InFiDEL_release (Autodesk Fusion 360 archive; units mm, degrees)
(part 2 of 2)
sketch "Sketch42" plane through (0, 0, -12.5) normal (0, 0, -1) x axis (1, 0, 0)
  line L1 (43.0529, -11.2074) -> (41.7955, -15.3363)
  curve K1 (43.2824, -10.9315) -> (43.0529, -11.2074)
  curve K2 (43.6391, -10.8945) -> (43.2824, -10.9315)
  line L2 (44.3673, -11.1162) -> (43.6391, -10.8945)
  curve K3 (44.6383, -11.3454) -> (44.3673, -11.1162)
  curve K4 (44.6643, -11.6992) -> (44.6383, -11.3454)
  line L3 (42.3458, -19.3124) -> (44.6643, -11.6992)
  curve K5 (42.1325, -19.5782) -> (42.3458, -19.3124)
  curve K6 (41.7789, -19.6156) -> (42.1325, -19.5782)
  line L4 (41.0358, -19.3893) -> (41.7789, -19.6156)
  curve K7 (40.7665, -19.156) -> (41.0358, -19.3893)
  curve K8 (40.7367, -18.813) -> (40.7665, -19.156)
  line L5 (40.7788, -18.6732) -> (40.7367, -18.813)
  curve K9 (39.6654, -18.874) -> (40.7788, -18.6732)
  curve K10 (38.3581, -18.6736) -> (39.6654, -18.874)
  curve K11 (36.5327, -17.1841) -> (38.3581, -18.6736)
  curve K12 (36.6028, -14.6019) -> (36.5327, -17.1841)
  line L6 (38.0961, -9.6984) -> (36.6028, -14.6019)
  curve K13 (38.3257, -9.4223) -> (38.0961, -9.6984)
  curve K14 (38.6824, -9.385) -> (38.3257, -9.4223)
  line L7 (39.3956, -9.6022) -> (38.6824, -9.385)
  curve K15 (39.6726, -9.8309) -> (39.3956, -9.6022)
  curve K16 (39.7079, -10.1887) -> (39.6726, -9.8309)
  line L8 (38.4271, -14.3945) -> (39.7079, -10.1887)
  line L9 (0, 0.8665) -> (2.0813, 0.2327)
  line L10 (0, -22) -> (0, 0.8665)
  line L11 (43.8534, -22) -> (0, -22)
  line L12 (46.793, -12.3472) -> (43.8534, -22)
  curve K17 (47.0029, -12.0701) -> (46.793, -12.3472)
  curve K18 (47.35, -12.0246) -> (47.0029, -12.0701)
  line L13 (48.1677, -12.2736) -> (47.35, -12.0246)
  curve K19 (48.4321, -12.5038) -> (48.1677, -12.2736)
  curve K20 (48.4503, -12.8519) -> (48.4321, -12.5038)
  line L14 (45.6644, -22) -> (48.4503, -12.8519)
  line L15 (50, -22) -> (45.6644, -22)
  line L16 (50, 2) -> (50, -22)
  line L17 (1.6466, 2) -> (50, 2)
  curve K21 (2.5546, 1.7334) -> (1.6466, 2)
  curve K22 (3.7364, 1.273) -> (2.5546, 1.7334)
  curve K23 (4.6822, 0.5429) -> (3.7364, 1.273)
  curve K24 (5.1744, -0.5786) -> (4.6822, 0.5429)
  curve K25 (4.9882, -2.2066) -> (5.1744, -0.5786)
  line L18 (2.5164, -10.3235) -> (4.9882, -2.2066)
  curve K26 (2.293, -10.5875) -> (2.5164, -10.3235)
  curve K27 (1.9343, -10.6218) -> (2.293, -10.5875)
  line L19 (1.176, -10.3909) -> (1.9343, -10.6218)
  curve K28 (0.8989, -10.1616) -> (1.176, -10.3909)
  curve K29 (0.8591, -9.8185) -> (0.8989, -10.1616)
  line L20 (3.3328, -1.6957) -> (0.8591, -9.8185)
  curve K30 (3.4789, -0.9974) -> (3.3328, -1.6957)
  curve K31 (3.3842, -0.5) -> (3.4789, -0.9974)
  curve K32 (2.9657, -0.1182) -> (3.3842, -0.5)
  curve K33 (2.0813, 0.2327) -> (2.9657, -0.1182)
  curve K34 (22.7149, -16.723) -> (22.7545, -17.0665)
  line L21 (23.0791, -15.5271) -> (22.7149, -16.723)
  curve K35 (23.3088, -15.2502) -> (23.0791, -15.5271)
  curve K36 (23.666, -15.2128) -> (23.3088, -15.2502)
  line L22 (24.4243, -15.4438) -> (23.666, -15.2128)
  curve K37 (24.7016, -15.6729) -> (24.4243, -15.4438)
  curve K38 (24.7364, -16.0318) -> (24.7016, -15.6729)
  line L23 (24.3722, -17.2277) -> (24.7364, -16.0318)
  curve K39 (24.1487, -17.4924) -> (24.3722, -17.2277)
  curve K40 (23.79, -17.5268) -> (24.1487, -17.4924)
  line L24 (23.0316, -17.2959) -> (23.79, -17.5268)
  curve K41 (22.7545, -17.0665) -> (23.0316, -17.2959)
  curve K42 (23.6897, -13.631) -> (23.7295, -13.9741)
  line L25 (26.0082, -6.0178) -> (23.6897, -13.631)
  curve K43 (26.2378, -5.7412) -> (26.0082, -6.0178)
  curve K44 (26.5947, -5.7039) -> (26.2378, -5.7412)
  line L26 (27.3079, -5.9211) -> (26.5947, -5.7039)
  curve K45 (27.585, -6.1502) -> (27.3079, -5.9211)
  curve K46 (27.6199, -6.5086) -> (27.585, -6.1502)
  line L27 (25.3014, -14.1218) -> (27.6199, -6.5086)
  curve K47 (25.078, -14.3861) -> (25.3014, -14.1218)
  curve K48 (24.7196, -14.4205) -> (25.078, -14.3861)
  line L28 (24.0064, -14.2033) -> (24.7196, -14.4205)
  curve K49 (23.7295, -13.9741) -> (24.0064, -14.2033)
  curve K50 (7.3751, -1.0358) -> (7.5956, -1.4466)
  line L29 (7.6051, -0.2805) -> (7.3751, -1.0358)
  curve K51 (7.7394, -0.0762) -> (7.6051, -0.2805)
  curve K52 (8.0125, -0.0118) -> (7.7394, -0.0762)
  curve K53 (8.5792, -0.1431) -> (8.0125, -0.0118)
  curve K54 (9.3638, -0.3569) -> (8.5792, -0.1431)
  curve K55 (10.1986, -0.5945) -> (9.3638, -0.3569)
  line L30 (10.9476, -0.8226) -> (10.1986, -0.5945)
  curve K56 (13.2215, -2.2584) -> (10.9476, -0.8226)
  curve K57 (13.381, -4.763) -> (13.2215, -2.2584)
  line L31 (11.6314, -10.5084) -> (13.381, -4.763)
  curve K58 (10.1082, -12.4846) -> (11.6314, -10.5084)
  curve K59 (7.4193, -12.4085) -> (10.1082, -12.4846)
  curve K60 (6.7389, -12.1918) -> (7.4193, -12.4085)
  curve K61 (5.872, -11.91) -> (6.7389, -12.1918)
  curve K62 (5.1061, -11.6512) -> (5.872, -11.91)
  curve K63 (4.5236, -11.4251) -> (5.1061, -11.6512)
  curve K64 (4.3429, -11.223) -> (4.5236, -11.4251)
  curve K65 (4.3429, -10.9929) -> (4.3429, -11.223)
  line L32 (4.5714, -10.2426) -> (4.3429, -10.9929)
  curve K66 (4.9887, -10.0068) -> (4.5714, -10.2426)
  line L33 (7.8674, -10.8835) -> (4.9887, -10.0068)
  curve K67 (8.7961, -11.0832) -> (7.8674, -10.8835)
  curve K68 (9.3618, -11.0016) -> (8.7961, -11.0832)
  curve K69 (9.7105, -10.6553) -> (9.3618, -11.0016)
  curve K70 (9.9754, -9.9992) -> (9.7105, -10.6553)
  line L34 (10.5641, -8.0661) -> (9.9754, -9.9992)
  line L35 (6.137, -6.7179) -> (10.5641, -8.0661)
  curve K71 (5.8591, -6.4896) -> (6.137, -6.7179)
  curve K72 (5.8184, -6.1476) -> (5.8591, -6.4896)
  line L36 (5.9899, -5.5846) -> (5.8184, -6.1476)
  curve K73 (6.2198, -5.3096) -> (5.9899, -5.5846)
  curve K74 (6.5768, -5.2734) -> (6.2198, -5.3096)
  line L37 (11.004, -6.6217) -> (6.5768, -5.2734)
  line L38 (11.7242, -4.2569) -> (11.004, -6.6217)
  curve K75 (11.871, -3.5559) -> (11.7242, -4.2569)
  curve K76 (11.7769, -3.0569) -> (11.871, -3.5559)
  curve K77 (11.3586, -2.6744) -> (11.7769, -3.0569)
  curve K78 (10.4742, -2.3233) -> (11.3586, -2.6744)
  line L39 (7.5956, -1.4466) -> (10.4742, -2.3233)
  curve K79 (14.1152, -9.2264) -> (13.7966, -11.452)
  line L40 (14.7287, -7.2118) -> (14.1152, -9.2264)
  curve K80 (15.7052, -5.1903) -> (14.7287, -7.2118)
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extrude "Extrude7" cut sketch "Sketch42" against normal blind 1
position "Position6"
sketch "Sketch43" plane through (0, 0, -12.5) normal (0, 0, -1) x axis (1, 0, 0)
  line L1 (43.0529, -11.2074) -> (41.7955, -15.3363)
  curve K1 (43.2824, -10.9315) -> (43.0529, -11.2074)
  curve K2 (43.6391, -10.8945) -> (43.2824, -10.9315)
  line L2 (44.3673, -11.1162) -> (43.6391, -10.8945)
  curve K3 (44.6383, -11.3454) -> (44.3673, -11.1162)
  curve K4 (44.6643, -11.6992) -> (44.6383, -11.3454)
  line L3 (42.3458, -19.3124) -> (44.6643, -11.6992)
  curve K5 (42.1325, -19.5782) -> (42.3458, -19.3124)
  curve K6 (41.7789, -19.6156) -> (42.1325, -19.5782)
  line L4 (41.0358, -19.3893) -> (41.7789, -19.6156)
  curve K7 (40.7665, -19.156) -> (41.0358, -19.3893)
  curve K8 (40.7367, -18.813) -> (40.7665, -19.156)
  line L5 (40.7788, -18.6732) -> (40.7367, -18.813)
  curve K9 (39.6654, -18.874) -> (40.7788, -18.6732)
  curve K10 (38.3581, -18.6736) -> (39.6654, -18.874)
  curve K11 (36.5327, -17.1841) -> (38.3581, -18.6736)
  curve K12 (36.6028, -14.6019) -> (36.5327, -17.1841)
  line L6 (38.0961, -9.6984) -> (36.6028, -14.6019)
  curve K13 (38.3257, -9.4223) -> (38.0961, -9.6984)
  curve K14 (38.6824, -9.385) -> (38.3257, -9.4223)
  line L7 (39.3956, -9.6022) -> (38.6824, -9.385)
  curve K15 (39.6726, -9.8309) -> (39.3956, -9.6022)
  curve K16 (39.7079, -10.1887) -> (39.6726, -9.8309)
  line L8 (38.4271, -14.3945) -> (39.7079, -10.1887)
  line L9 (0, 0.8665) -> (2.0813, 0.2327)
  line L10 (0, -22) -> (0, 0.8665)
  line L11 (43.8534, -22) -> (0, -22)
  line L12 (46.793, -12.3472) -> (43.8534, -22)
  curve K17 (47.0029, -12.0701) -> (46.793, -12.3472)
  curve K18 (47.35, -12.0246) -> (47.0029, -12.0701)
  line L13 (48.1677, -12.2736) -> (47.35, -12.0246)
  curve K19 (48.4321, -12.5038) -> (48.1677, -12.2736)
  curve K20 (48.4503, -12.8519) -> (48.4321, -12.5038)
  line L14 (45.6644, -22) -> (48.4503, -12.8519)
  line L15 (50, -22) -> (45.6644, -22)
  line L16 (50, 2) -> (50, -22)
  line L17 (1.6466, 2) -> (50, 2)
  curve K21 (2.5546, 1.7334) -> (1.6466, 2)
  curve K22 (3.7364, 1.273) -> (2.5546, 1.7334)
  curve K23 (4.6822, 0.5429) -> (3.7364, 1.273)
  curve K24 (5.1744, -0.5786) -> (4.6822, 0.5429)
  curve K25 (4.9882, -2.2066) -> (5.1744, -0.5786)
  line L18 (2.5164, -10.3235) -> (4.9882, -2.2066)
  curve K26 (2.293, -10.5875) -> (2.5164, -10.3235)
  curve K27 (1.9343, -10.6218) -> (2.293, -10.5875)
  line L19 (1.176, -10.3909) -> (1.9343, -10.6218)
  curve K28 (0.8989, -10.1616) -> (1.176, -10.3909)
  curve K29 (0.8591, -9.8185) -> (0.8989, -10.1616)
  line L20 (3.3328, -1.6957) -> (0.8591, -9.8185)
  curve K30 (3.4789, -0.9974) -> (3.3328, -1.6957)
  curve K31 (3.3842, -0.5) -> (3.4789, -0.9974)
  curve K32 (2.9657, -0.1182) -> (3.3842, -0.5)
  curve K33 (2.0813, 0.2327) -> (2.9657, -0.1182)
  curve K34 (22.7149, -16.723) -> (22.7545, -17.0665)
  line L21 (23.0791, -15.5271) -> (22.7149, -16.723)
  curve K35 (23.3088, -15.2502) -> (23.0791, -15.5271)
  curve K36 (23.666, -15.2128) -> (23.3088, -15.2502)
  line L22 (24.4243, -15.4438) -> (23.666, -15.2128)
  curve K37 (24.7016, -15.6729) -> (24.4243, -15.4438)
  curve K38 (24.7364, -16.0318) -> (24.7016, -15.6729)
  line L23 (24.3722, -17.2277) -> (24.7364, -16.0318)
  curve K39 (24.1487, -17.4924) -> (24.3722, -17.2277)
  curve K40 (23.79, -17.5268) -> (24.1487, -17.4924)
  line L24 (23.0316, -17.2959) -> (23.79, -17.5268)
  curve K41 (22.7545, -17.0665) -> (23.0316, -17.2959)
  curve K42 (23.6897, -13.631) -> (23.7295, -13.9741)
  line L25 (26.0082, -6.0178) -> (23.6897, -13.631)
  curve K43 (26.2378, -5.7412) -> (26.0082, -6.0178)
  curve K44 (26.5947, -5.7039) -> (26.2378, -5.7412)
  line L26 (27.3079, -5.9211) -> (26.5947, -5.7039)
  curve K45 (27.585, -6.1502) -> (27.3079, -5.9211)
  curve K46 (27.6199, -6.5086) -> (27.585, -6.1502)
  line L27 (25.3014, -14.1218) -> (27.6199, -6.5086)
  curve K47 (25.078, -14.3861) -> (25.3014, -14.1218)
  curve K48 (24.7196, -14.4205) -> (25.078, -14.3861)
  line L28 (24.0064, -14.2033) -> (24.7196, -14.4205)
  curve K49 (23.7295, -13.9741) -> (24.0064, -14.2033)
  curve K50 (7.3751, -1.0358) -> (7.5956, -1.4466)
  line L29 (7.6051, -0.2805) -> (7.3751, -1.0358)
  curve K51 (7.7394, -0.0762) -> (7.6051, -0.2805)
  curve K52 (8.0125, -0.0118) -> (7.7394, -0.0762)
  curve K53 (8.5792, -0.1431) -> (8.0125, -0.0118)
  curve K54 (9.3638, -0.3569) -> (8.5792, -0.1431)
  curve K55 (10.1986, -0.5945) -> (9.3638, -0.3569)
  line L30 (10.9476, -0.8226) -> (10.1986, -0.5945)
  curve K56 (13.2215, -2.2584) -> (10.9476, -0.8226)
  curve K57 (13.381, -4.763) -> (13.2215, -2.2584)
  line L31 (11.6314, -10.5084) -> (13.381, -4.763)
  curve K58 (10.1082, -12.4846) -> (11.6314, -10.5084)
  curve K59 (7.4193, -12.4085) -> (10.1082, -12.4846)
  curve K60 (6.7389, -12.1918) -> (7.4193, -12.4085)
  curve K61 (5.872, -11.91) -> (6.7389, -12.1918)
  curve K62 (5.1061, -11.6512) -> (5.872, -11.91)
  curve K63 (4.5236, -11.4251) -> (5.1061, -11.6512)
  curve K64 (4.3429, -11.223) -> (4.5236, -11.4251)
  curve K65 (4.3429, -10.9929) -> (4.3429, -11.223)
  line L32 (4.5714, -10.2426) -> (4.3429, -10.9929)
  curve K66 (4.9887, -10.0068) -> (4.5714, -10.2426)
  line L33 (7.8674, -10.8835) -> (4.9887, -10.0068)
  curve K67 (8.7961, -11.0832) -> (7.8674, -10.8835)
  curve K68 (9.3618, -11.0016) -> (8.7961, -11.0832)
  curve K69 (9.7105, -10.6553) -> (9.3618, -11.0016)
  curve K70 (9.9754, -9.9992) -> (9.7105, -10.6553)
  line L34 (10.5641, -8.0661) -> (9.9754, -9.9992)
  line L35 (6.137, -6.7179) -> (10.5641, -8.0661)
  curve K71 (5.8591, -6.4896) -> (6.137, -6.7179)
  curve K72 (5.8184, -6.1476) -> (5.8591, -6.4896)
  line L36 (5.9899, -5.5846) -> (5.8184, -6.1476)
  curve K73 (6.2198, -5.3096) -> (5.9899, -5.5846)
  curve K74 (6.5768, -5.2734) -> (6.2198, -5.3096)
  line L37 (11.004, -6.6217) -> (6.5768, -5.2734)
  line L38 (11.7242, -4.2569) -> (11.004, -6.6217)
  curve K75 (11.871, -3.5559) -> (11.7242, -4.2569)
  curve K76 (11.7769, -3.0569) -> (11.871, -3.5559)
  curve K77 (11.3586, -2.6744) -> (11.7769, -3.0569)
  curve K78 (10.4742, -2.3233) -> (11.3586, -2.6744)
  line L39 (7.5956, -1.4466) -> (10.4742, -2.3233)
  curve K79 (14.1152, -9.2264) -> (13.7966, -11.452)
  line L40 (14.7287, -7.2118) -> (14.1152, -9.2264)
  curve K80 (15.7052, -5.1903) -> (14.7287, -7.2118)
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  point P172 (0.5507, 0.6988)
  point P41 (1.6466, 2)
  point P176 (1.6466, 2)
  coincident L9 P172
  coincident P41 P176
extrude "Extrude8" cut sketch "Sketch43" to an object
sketch "Sketch44" plane through (0, -2, 0) normal (0, -1, 0) x axis (1, 0, 0)
  curve K1 (39.523, -8.8538) -> (26.677, -8.8538)
  line L1 (21.1, 2) -> (21.1, -2)
  curve K2 (26.677, 8.8538) -> (39.523, 8.8538)
  line L2 (45.1, -2) -> (45.1, 2)
  line L3 (1.6466, -11.5) -> (-1.7321, -11.5)
  line L4 (1.6466, -12.5) -> (1.6466, -11.5)
  line L5 (50, -12.5) -> (1.6466, -12.5)
  line L6 (52, 10.5) -> (52, -10.5)
  line L7 (0, 12.5) -> (50, 12.5)
  line L8 (-2, -10.5) -> (-2, 10.5)
  line L9 (2.6466, -12.5) -> (1.6466, -11.5)
  arc A1 centre (28.1, -2) radius 7 clockwise from (26.677, -8.8538) to (21.1, -2)
  arc A2 centre (28.1, 2) radius 7 clockwise from (21.1, 2) to (26.677, 8.8538)
  arc A3 centre (38.1, 2) radius 7 clockwise from (39.523, 8.8538) to (45.1, 2)
  arc A4 centre (38.1, -2) radius 7 clockwise from (45.1, -2) to (39.523, -8.8538)
  circle C1 centre (2.5, -8) radius 2
  circle C2 centre (47.5, 8) radius 2
  circle C3 centre (2.5, 8) radius 2
  circle C4 centre (47.5, -8) radius 2
  arc A5 centre (50, -10.5) radius 2 clockwise from (52, -10.5) to (50, -12.5)
  arc A6 centre (50, 10.5) radius 2 clockwise from (50, 12.5) to (52, 10.5)
  arc A7 centre (0, 10.5) radius 2 clockwise from (-2, 10.5) to (0, 12.5)
  arc A8 centre (0, -10.5) radius 2 clockwise from (-1.7321, -11.5) to (-2, -10.5)
  point P19 (1.6466, -11.5)
  point P32 (1.6466, -11.5)
  point P33 (2.6466, -12.5)
  coincident P19 P32
  coincident L5 P33
  dimension "d323" angle L5 L9 = 45
extrude "Extrude9" cut sketch "Sketch44" profile of L4 L5 L9 against normal blind 0.9
fillet "Fillet4" radius 1
fillet "Fillet5" radius 1
sketch "Sketch45" plane through (52, 0, 0) normal (1, 0, 0) x axis (0, 1, 0)
extrude "Extrude10" cut sketch "Sketch45" against normal blind 0.5
sketch "Sketch46" plane through (-2, 0, 0) normal (-1, 0, 0) x axis (0, -1, 0)
  line L1 (2, -10.5) -> (1.4756, -10.5)
  line L2 (2, 10.5) -> (2, -10.5)
  line L3 (-22, 10.5) -> (2, 10.5)
  line L4 (-22, -10.5) -> (-22, 10.5)
  line L5 (1.4756, -10.5) -> (-22, -10.5)
  curve K1 (-12.7649, -6.0249) -> (-15.8985, 0)
  curve K2 (-15.8985, 0) -> (-11.9399, 6.5262)
  curve K3 (-11.9399, 6.5262) -> (-7.5162, -7.2874)
  curve K4 (-9.2562, -8.9692) -> (-7.5162, -7.2874)
  curve K5 (-12.7649, -6.0249) -> (-10.8438, -8.9692)
  curve K6
  curve K7
  curve K8
  curve K9
  arc A1 centre (-10.05, -6) radius 3.0735 clockwise from (-9.2562, -8.9692) to (-10.8438, -8.9692)
  point P6 (-22, -10.5)
  point P7 (-15.8985, 0)
  coincident L3
  coincident P6
  collinear L4 K8
  coincident P7
extrude "Extrude11" cut sketch "Sketch46" against normal blind 0.5
copy_paste_bodies "CutPasteBodies1"
sketch "Pre-defeature detail" plane through (0, 0, 0) normal (0, 0, 1) x axis (1, 0, 0)
  circle C1 centre (33.1, 4.8) radius 1.45
  arc A1 centre (33.0795, 16.0881) radius 1.45 clockwise from (34.3635, 15.4145) to (34.4161, 16.6502)
delete_face "DeleteFace1"
sketch "Sketch48" plane through (0, 0, 0) normal (0, 0, 1) x axis (1, 0, 0)
  line L1 (33.1, 15.8892) -> (33.1, 4.8)
  circle C1 centre (33.1, 4.8) radius 5
  circle C2 centre (33.1, 15.8892) radius 5
  circle C3 centre (33.1, 15.8892) radius 1.45
  point P2 (33.1, 4.8)
  point P3 (33.1, 4.8)
  point P4 (33.1, 4.8)
  point P5 (33.1, 15.8892)
  point P6 (33.1, 15.8892)
  point P7 (33.1, 10.8892)
  point P8 (33.1, 9.8)
  point P9 (33.1, 15.8892)
  point P10 (33.0795, 16.0881)
  coincident P2 P3
  coincident P3 P4
  vertical L1
  coincident P5 P6
  coincident C2 P7
  coincident L1 P7
  coincident C1 P8
  coincident L1 P8
  concentric C2 C3
  dimension "d336" diameter C1 = 10
  dimension "d337" diameter C2 = 10
  dimension "d340" diameter C3 = 2.9 (= "PinPressDia")
  dimension "d343" distance P9 P10 = 0.2 (= "RollerCenter - Roller_Center_dyn")
extrude "Extrude3" cut sketch "Sketch48" profile of C3 distance 17
sketch "Sketch49" plane through (0, 0, 0) normal (0, 0, 1) x axis (1, 0, 0)
  line L1 (38.8567, 10.6) -> (37.35, 11.4699)
  line L2 (39.85, 5.4) -> (39.85, 15.8)
  line L3 (39.85, 10.6) -> (38.8567, 10.6)
  line L4 (39.85, 11.4699) -> (37.35, 11.4699)
  line L5 (40.8433, 10.6) -> (42.35, 11.4699)
  line L6 (39.85, 10.6) -> (40.8433, 10.6)
  circle C1 centre (39.85, 15.8) radius 5
  point P3 (37.35, 11.4699)
  point P2 (39.85, 15.8)
  point P5 (39.85, 15.8)
  point P7 (39.85, 10.6)
  point P8 (39.85, 11.4699)
  point P9 (39.85, 10.8)
  point P10 (42.35, 11.4699)
  point P4 (38.8567, 10.6)
  point P11 (40.8433, 10.6)
  point P12 (39.85, 10.6)
  coincident C1 P3
  coincident P2 P5
  vertical L2
  midpoint L2 P7
  coincident L2 P8
  perpendicular L2 L4
  horizontal L3
  coincident C1 P9
  coincident L2 P9
  tangent C1 L1
  symmetric P3 L2 P10
  symmetric P4 L2 P11
  symmetric L2 P7 P12
  dimension "d344" distance L3 P9 = 0.2
  dimension "d345" angle L1 L3 = 30
extrude "Extrude4" sketch "Sketch49" profile of C1 L1 L2 L3 L5 L6 no distance stored
extrude "Extrude5" sketch "Sketch49" profile of C1 L1 L2 L3 L5 L6 no distance stored
copy_paste_bodies "CopyPasteBodies1"
move "Move2"
copy_paste_bodies "CutPasteBodies1"
combine "Combine1"
remove_instance "RemoveInstance6"
remove_instance "RemoveInstance7"
remove_instance "RemoveInstance8"
remove_instance "RemoveInstance9"
remove_instance "RemoveInstance10"
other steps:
base_feature "Base Feature1" bodies "SpringPlunger"
base_feature "Base Feature2" bodies "SpringPlunger (1)", "SpringPlungerExtender"
base_feature "Base Feature1" bodies "PTFE (1)"
base_feature "Base Feature1" bodies "PTFE"
base_feature "Base Feature2" bodies "PTFE"
base_feature "Base Feature1" bodies "Filament"
base_feature "Base Feature2" bodies "Filament (1)"
base_feature "Base Feature1" bodies "BlockClearance"
base_feature "Base Feature2" bodies "Filament"
base_feature "Base Feature1" bodies "LeverPlastic"
base_feature "Base Feature1" bodies "Block"
base_feature "Base Feature2" bodies "SpringPlunger"
create_component "CreateComponent1"
create_component "CreateComponent1"
create_component "CreateComponent2"
create_component "CreateComponent1"
create_component "CreateComponent2"
create_component "CreateComponent3"
create_component "CreateComponent4"
create_component "CreateComponent5"
remove_body "RemoveBody1"
create_component "CreateComponent6"
joint_origin "JointOrigin1"
joint_origin "JointOrigin1"
joint_origin "JointOrigin2"
joint_origin "JointOrigin2"
remove_instance "RemoveInstance1"
remove_instance "RemoveInstance2"
remove_instance "RemoveInstance3"
create_component "CreateComponent7"
remove_body "RemoveBody2"
create_component "CreateComponent8"
joint_origin "JointOrigin1"
joint_origin "JointOrigin1"
remove_instance "RemoveInstance4"
create_component "CreateComponent9"
joint_origin "JointOrigin1"
joint_origin "JointOrigin2"
remove_instance "RemoveInstance5"
joint_origin "JointOrigin4"
joint_origin "JointOrigin4"
create_component "CreateComponent10"
remove_body "RemoveBody3"
create_component "CreateComponent11"
remove_body "RemoveBody4"
create_component "CreateComponent12"
remove_body "RemoveBody5"
create_component "CreateComponent13"
remove_body "RemoveBody6"
remove_body "RemoveBody1"
create_component "CreateComponent14"
remove_body "RemoveBody7"
remove_body "RemoveBody1"
remove_body "RemoveBody8"
joint_origin "JointOrigin6"
remove_body "RemoveBody1"
remove_body "RemoveBody9"
named bodies: "LeverPlastic", "Filament", "PTFE", "PTFEGuide", "PTFEGuide (1)", "PTFE (1)", "LeverClearance", "BlockClearance", "Block", "SpringPlunger", "PTFEClearance", "PTFEClearance (1)", "Filament (1)", "SpringPlunger (1)", "SpringPlungerExtender"

design "filaSens"
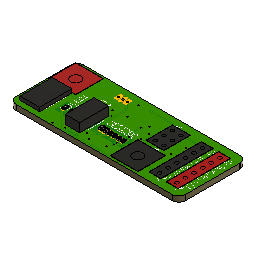
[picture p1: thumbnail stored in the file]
sketch "Outline" plane through (0, 0, 0) normal (0, 0, 1) x axis (1, 0, 0)
  line L1 (48, 0) -> (2, 0)
  line L2 (48.1743, 0.0076) -> (48, 0)
  line L3 (50, 18) -> (50, 2)
  line L4 (49.9924, 18.1743) -> (50, 18)
  line L5 (2, 20) -> (48, 20)
  line L6 (1.8257, 19.9924) -> (2, 20)
  line L7 (0, 2) -> (0, 18)
  arc A1 centre (2, 2) radius 2 clockwise from (2, 0) to (0, 2)
  arc A2 centre (48, 2) radius 2 clockwise from (50, 2) to (48.1743, 0.0076)
  arc A3 centre (48, 18) radius 2 clockwise from (48, 20) to (49.9924, 18.1743)
  arc A4 centre (2, 18) radius 2 clockwise from (0, 18) to (1.8257, 19.9924)
canvas "Canvas1"
canvas "Canvas2"
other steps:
base_feature "Base Feature1"
extrude "Extrude1" sketch "Outline" blind 1.57 bodies "Board"
base_feature "Base Feature1"
box_primitive "BoxPrimitive1" DistanceX 9.5 DistanceY 5.8 DistanceZ 1.1133 OffsetDistanceX 0 OffsetDistanceY 0
box_primitive "BoxPrimitive1" DistanceX 4.1032 DistanceY 2.6224 DistanceZ 0.1 OffsetDistanceX 0 OffsetDistanceY 0
box_primitive "BoxPrimitive1" DistanceX 4.31 DistanceY 8.508 DistanceZ 2.5897 OffsetDistanceX 0 OffsetDistanceY 0
box_primitive "BoxPrimitive1" DistanceX 7.7724 DistanceY 5.2324 DistanceZ 0.1 OffsetDistanceX 0 OffsetDistanceY 0
box_primitive "BoxPrimitive1" DistanceX 8.128 DistanceY 8.128 DistanceZ 0.1 OffsetDistanceX 0 OffsetDistanceY 0
box_primitive "BoxPrimitive1" DistanceX 15.3924 DistanceY 3.4544 DistanceZ 0.1 OffsetDistanceX 0 OffsetDistanceY 0
base_feature "Base Feature1"
base_feature "Base Feature1"
pcbextrude "PCBExtrude1"
create_component "CreateComponent1"
create_component "CreateComponent2"
create_component "CreateComponent1"
create_component "CreateComponent1"
create_component "CreateComponent2"
create_component "CreateComponent3"
create_component "CreateComponent4"
create_component "CreateComponent5"
create_component "CreateComponent6"
create_component "CreateComponent7"
create_component "CreateComponent8"
create_component "CreateComponent9"
as_built_joint "As-built1"
named bodies: "Board"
